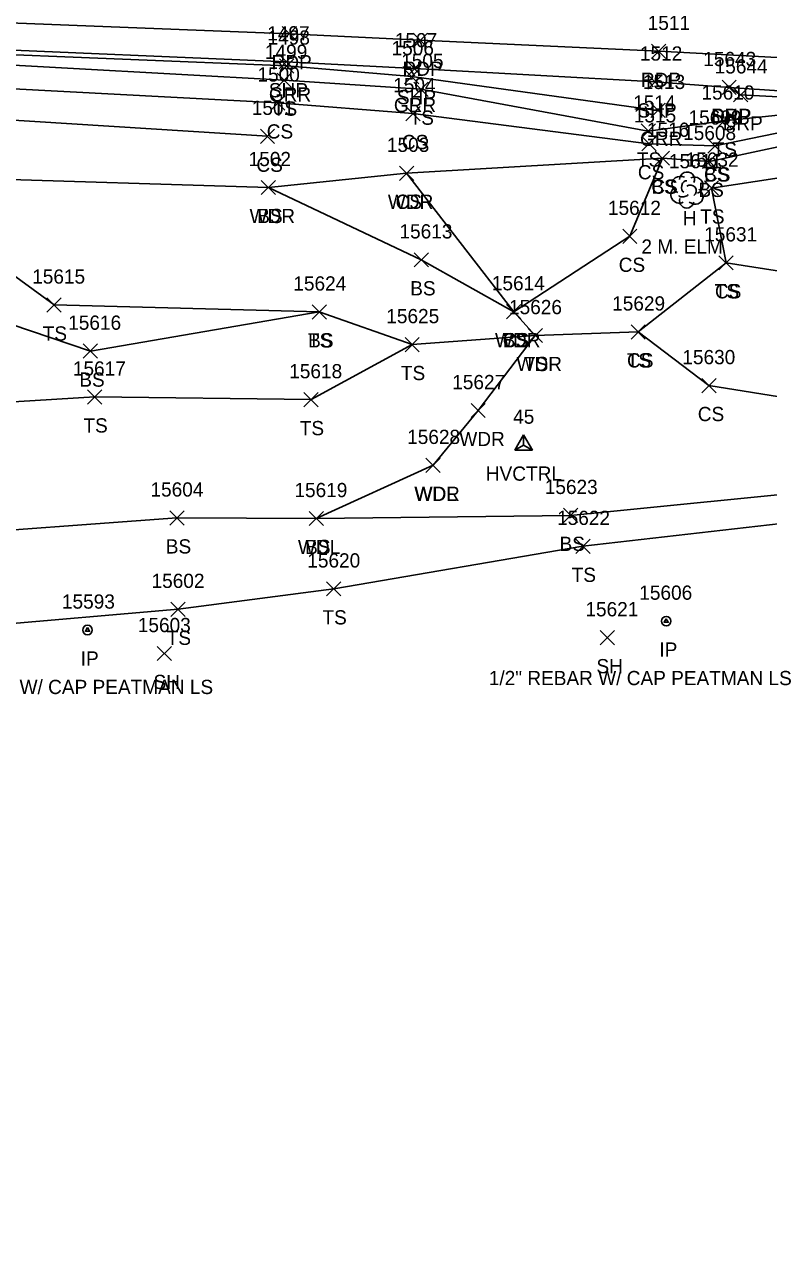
# Model space of a CAD drawing. Extents: x 1606530 to 1613020, y 784959 to 789666.
# Drawn here: x 1609388.2 to 1609492.8, y 788263.1 to 788433.6 of the extents above; entities that cross this region are included whole.
import ezdxf

# ---------------------------------------------------------------- set-up
doc = ezdxf.new("R2010")
doc.units = 0
for name, color, linetype in [('C_A', 7, 'Continuous'), ('C_I', 7, 'Continuous'), ('CPSM', 7, 'Continuous'), ('L_A', 7, 'Continuous'), ('L_C', 7, 'Continuous'), ('L_I', 7, 'Continuous'), ('L_TIC', 7, 'Continuous'), ('LAWA', 7, 'Continuous'), ('LELB', 7, 'Continuous'), ('LTD', 7, 'Continuous'), ('M_A', 7, 'Continuous'), ('M_C', 7, 'Continuous'), ('M_I', 7, 'Continuous'), ('MPIR', 7, 'Continuous'), ('P_A', 7, 'Continuous'), ('P_I', 7, 'Continuous'), ('P_TIC', 7, 'Continuous'), ('PET', 7, 'Continuous'), ('PSP', 7, 'Continuous'), ('R_A', 7, 'Continuous'), ('R_I', 7, 'Continuous'), ('R_TIC', 7, 'Continuous'), ('RDP', 7, 'Continuous'), ('RGR', 7, 'Continuous')]:
    doc.layers.add(name, color=color, linetype=linetype)

msp = doc.modelspace()

# ---------------------------------------------------------------- linework, layer by layer
at = {"layer": 'CPSM'}
for p, q in [((1609457.08, 788373.72), (1609458.33, 788375.89)), ((1609459.58, 788373.72), (1609458.33, 788375.89)), ((1609458.33, 788374.44), (1609458.33, 788375.89)), ((1609457.08, 788373.72), (1609458.33, 788374.44)), ((1609457.08, 788373.72), (1609459.58, 788373.72)), ((1609458.33, 788374.44), (1609458.33, 788374.44)), ((1609458.33, 788374.44), (1609459.58, 788373.72))]:
    msp.add_line(p, q, dxfattribs=at)
at = {"layer": 'L_TIC'}
for points in [[(1609423.69, 788424.72), (1609425.69, 788426.72)], [(1609425.69, 788424.72), (1609423.69, 788426.72)], [(1609442.9, 788423.45), (1609444.9, 788425.45)], [(1609444.9, 788423.45), (1609442.9, 788425.45)], [(1609422.8, 788421.52), (1609424.8, 788423.52)], [(1609424.8, 788421.52), (1609422.8, 788423.52)], [(1609441.79, 788420.03), (1609443.79, 788422.03)], [(1609443.79, 788420.03), (1609441.79, 788422.03)], [(1609474.84, 788417.57), (1609476.84, 788419.57)], [(1609476.84, 788417.57), (1609474.84, 788419.57)], [(1609485.48, 788418.99), (1609487.48, 788420.99)], [(1609487.48, 788418.99), (1609485.48, 788420.99)], [(1609421.35, 788416.84), (1609423.35, 788418.84)], [(1609423.35, 788416.84), (1609421.35, 788418.84)], [(1609474.94, 788415.79), (1609476.94, 788417.79)], [(1609476.94, 788415.79), (1609474.94, 788417.79)], [(1609484.22, 788415.48), (1609486.22, 788417.48)], [(1609486.22, 788415.48), (1609484.22, 788417.48)], [(1609484.22, 788415.48), (1609486.22, 788417.48)], [(1609486.22, 788415.48), (1609484.22, 788417.48)], [(1609476.83, 788413.76), (1609478.83, 788415.76)], [(1609478.83, 788413.76), (1609476.83, 788415.76)], [(1609476.83, 788413.76), (1609478.83, 788415.76)], [(1609478.83, 788413.76), (1609476.83, 788415.76)], [(1609483.45, 788413.31), (1609485.45, 788415.31)], [(1609485.45, 788413.31), (1609483.45, 788415.31)], [(1609483.45, 788413.31), (1609485.45, 788415.31)], [(1609485.45, 788413.31), (1609483.45, 788415.31)], [(1609440.9, 788411.64), (1609442.9, 788413.64)], [(1609442.9, 788411.64), (1609440.9, 788413.64)], [(1609440.9, 788411.64), (1609442.9, 788413.64)], [(1609442.9, 788411.64), (1609440.9, 788413.64)], [(1609421.47, 788409.64), (1609423.47, 788411.64)], [(1609423.47, 788409.64), (1609421.47, 788411.64)], [(1609421.47, 788409.64), (1609423.47, 788411.64)], [(1609423.47, 788409.64), (1609421.47, 788411.64)], [(1609483.73, 788409.56), (1609485.73, 788411.56)], [(1609485.73, 788409.56), (1609483.73, 788411.56)], [(1609472.25, 788402.78), (1609474.25, 788404.78)], [(1609474.25, 788402.78), (1609472.25, 788404.78)], [(1609442.96, 788399.48), (1609444.96, 788401.48)], [(1609444.96, 788399.48), (1609442.96, 788401.48)], [(1609485.77, 788399.06), (1609487.77, 788401.06)], [(1609487.77, 788399.06), (1609485.77, 788401.06)], [(1609485.77, 788399.06), (1609487.77, 788401.06)], [(1609487.77, 788399.06), (1609485.77, 788401.06)], [(1609391.36, 788393.13), (1609393.36, 788395.13)], [(1609393.36, 788393.13), (1609391.36, 788395.13)], [(1609428.62, 788392.16), (1609430.62, 788394.16)], [(1609430.62, 788392.16), (1609428.62, 788394.16)], [(1609428.62, 788392.16), (1609430.62, 788394.16)], [(1609430.62, 788392.16), (1609428.62, 788394.16)], [(1609455.94, 788392.19), (1609457.94, 788394.19)], [(1609457.94, 788392.19), (1609455.94, 788394.19)], [(1609455.94, 788392.19), (1609457.94, 788394.19)], [(1609457.94, 788392.19), (1609455.94, 788394.19)], [(1609455.94, 788392.19), (1609457.94, 788394.19)], [(1609457.94, 788392.19), (1609455.94, 788394.19)], [(1609458.97, 788388.84), (1609460.97, 788390.84)], [(1609460.97, 788388.84), (1609458.97, 788390.84)], [(1609458.97, 788388.84), (1609460.97, 788390.84)], [(1609460.97, 788388.84), (1609458.97, 788390.84)], [(1609473.42, 788389.35), (1609475.42, 788391.35)], [(1609475.42, 788389.35), (1609473.42, 788391.35)], [(1609473.42, 788389.35), (1609475.42, 788391.35)], [(1609475.42, 788389.35), (1609473.42, 788391.35)], [(1609441.68, 788387.57), (1609443.68, 788389.57)], [(1609443.68, 788387.57), (1609441.68, 788389.57)], [(1609441.68, 788387.57), (1609443.68, 788389.57)], [(1609443.68, 788387.57), (1609441.68, 788389.57)], [(1609396.47, 788386.65), (1609398.47, 788388.65)], [(1609398.47, 788386.65), (1609396.47, 788388.65)], [(1609483.36, 788381.81), (1609485.36, 788383.81)], [(1609485.36, 788381.81), (1609483.36, 788383.81)], [(1609397.08, 788380.21), (1609399.08, 788382.21)], [(1609399.08, 788380.21), (1609397.08, 788382.21)], [(1609427.47, 788379.83), (1609429.47, 788381.83)], [(1609429.47, 788379.83), (1609427.47, 788381.83)], [(1609450.94, 788378.3), (1609452.94, 788380.3)], [(1609452.94, 788378.3), (1609450.94, 788380.3)], [(1609444.61, 788370.6), (1609446.61, 788372.6)], [(1609446.61, 788370.6), (1609444.61, 788372.6)], [(1609444.61, 788370.6), (1609446.61, 788372.6)], [(1609446.61, 788370.6), (1609444.61, 788372.6)], [(1609408.62, 788363.21), (1609410.62, 788365.21)], [(1609410.62, 788363.21), (1609408.62, 788365.21)], [(1609428.2, 788363.13), (1609430.2, 788365.13)], [(1609430.2, 788363.13), (1609428.2, 788365.13)], [(1609428.2, 788363.13), (1609430.2, 788365.13)], [(1609430.2, 788363.13), (1609428.2, 788365.13)], [(1609463.94, 788363.57), (1609465.94, 788365.57)], [(1609465.94, 788363.57), (1609463.94, 788365.57)], [(1609465.67, 788359.22), (1609467.67, 788361.22)], [(1609467.67, 788359.22), (1609465.67, 788361.22)], [(1609430.66, 788353.24), (1609432.66, 788355.24)], [(1609432.66, 788353.24), (1609430.66, 788355.24)], [(1609408.78, 788350.37), (1609410.78, 788352.37)], [(1609410.78, 788350.37), (1609408.78, 788352.37)], [(1609469.08, 788346.38), (1609471.08, 788348.38)], [(1609471.08, 788346.38), (1609469.08, 788348.38)], [(1609406.85, 788344.16), (1609408.85, 788346.16)], [(1609408.85, 788344.16), (1609406.85, 788346.16)]]:
    msp.add_lwpolyline(points, dxfattribs=at)
at = {"layer": 'LAWA'}
for points in [[(1609030.56, 788292.64), (1609056.03, 788324.44), (1609082.56, 788354.61), (1609090.16, 788369.42), (1609097.26, 788381.32), (1609109.23, 788386.03), (1609115.48, 788389.16), (1609124.65, 788392.27), (1609168.82, 788397.24), (1609199.02, 788403.22), (1609247.62, 788406.18), (1609289.08, 788410.02), (1609331.31, 788409.89), (1609380.07, 788411.97), (1609422.47, 788410.64), (1609441.9, 788412.64), (1609456.94, 788393.19), (1609459.97, 788389.84), (1609451.94, 788379.3), (1609445.61, 788371.6)], [(1609429.2, 788364.13), (1609445.61, 788371.6)]]:
    msp.add_lwpolyline(points, dxfattribs=at)
at = {"layer": 'LELB'}
for points in [[(1608830.7, 788263.06), (1608870.16, 788285.39), (1608903.61, 788303.66), (1608913.17, 788310.86), (1608944.69, 788327.51), (1608982.09, 788348.33), (1609025.65, 788367.84), (1609062.43, 788383.44), (1609080.36, 788388.45), (1609093.56, 788391.85), (1609111.49, 788398.34), (1609124.29, 788403.55), (1609165.33, 788413.89), (1609196.53, 788419.38), (1609241.91, 788424.94), (1609287.83, 788428.62), (1609331.16, 788428.8), (1609379, 788428.23), (1609424.69, 788425.72), (1609443.9, 788424.45), (1609475.84, 788418.57), (1609486.48, 788419.99), (1609502.63, 788421.7)], [(1609108.11, 788392.39), (1609124.69, 788397.48), (1609165.9, 788409.88), (1609197.34, 788410.75), (1609242.01, 788420.69), (1609288.52, 788423.98), (1609330.87, 788426.64), (1609378.66, 788424.92), (1609423.8, 788422.52), (1609442.79, 788421.03), (1609475.94, 788416.79), (1609485.22, 788416.48)], [(1609199.02, 788403.22), (1609245.4, 788416.55), (1609288, 788417.43), (1609333.16, 788421.05), (1609378.48, 788420.63), (1609422.35, 788417.84)], [(1609485.22, 788416.48), (1609502.09, 788419.94), (1609505.42, 788420.27), (1609505.55, 788418.27)], [(1609229.47, 788383.53), (1609235.87, 788391.77), (1609234.95, 788395.09), (1609256.53, 788397.81), (1609290, 788390.61), (1609315.27, 788387.55), (1609343.3, 788388.82), (1609351.97, 788404.1), (1609376.56, 788405.69), (1609392.36, 788394.13), (1609429.62, 788393.16), (1609442.68, 788388.57), (1609459.97, 788389.84), (1609474.42, 788390.35), (1609486.77, 788400.06), (1609484.73, 788410.56), (1609507.1, 788413.97), (1609507.85, 788418.71)], [(1609484.45, 788414.31), (1609501.55, 788417.96), (1609505.55, 788418.27)], [(1609441.9, 788412.64), (1609477.83, 788414.76), (1609473.25, 788403.78), (1609456.94, 788393.19)], [(1609477.83, 788414.76), (1609484.45, 788414.31)], [(1609422.47, 788410.64), (1609443.96, 788400.48), (1609456.94, 788393.19)], [(1609486.77, 788400.06), (1609518.48, 788395.11)], [(1609343.3, 788388.82), (1609372.31, 788396.17), (1609397.47, 788387.65), (1609429.62, 788393.16)], [(1609235.87, 788391.77), (1609256.08, 788384.31), (1609291.75, 788375.34), (1609316.49, 788370.01), (1609344.99, 788380.11), (1609370.61, 788379.55), (1609398.08, 788381.21), (1609428.47, 788380.83), (1609442.68, 788388.57)], [(1609474.42, 788390.35), (1609484.36, 788382.81), (1609503.91, 788379.7), (1609526.85, 788382.89)], [(1609374.03, 788361.62), (1609409.62, 788364.21), (1609429.2, 788364.13), (1609464.94, 788364.57), (1609503.84, 788368.43), (1609529.95, 788369.13)], [(1609382.71, 788349.03), (1609409.78, 788351.37), (1609431.66, 788354.24), (1609466.67, 788360.22), (1609502.72, 788364.36), (1609529.95, 788369.13)]]:
    msp.add_lwpolyline(points, dxfattribs=at)
at = {"layer": 'LTD'}
msp.add_line((1609481.26, 788410.34), (1609481.26, 788410.34), dxfattribs=at)
msp.add_line((1609481.26, 788410.34), (1609481.26, 788410.34), dxfattribs=at)
msp.add_arc((1609481.3, 788411.77), 1.05, 335.5272, 180.9563, dxfattribs=at)
for centre, major_axis, ratio, start_param, end_param in [((1609480.46, 788411.01), (1.21, -0.51), 0.895232, 1.570796, 4.712389), ((1609481.05, 788410.8), (-0.208, -0.792), 0.645439, 3.141593, 6.283185), ((1609481.76, 788410.17), (-0.5, 0.667), 0.989748, 3.141593, 6.283185), ((1609482.3, 788410.92), (-1.14, -0.48), 0.949671, 1.570796, 4.712389), ((1609480.17, 788409.63), (0.58, -1.04), 0.959034, 3.141593, 6.283185), ((1609480.8, 788409.59), (-0.625, -0.083), 0.423636, 0, 3.141593), ((1609482.26, 788409.51), (-1.09, 0.79), 0.841452, 1.570796, 4.712389), ((1609481.26, 788408.84), (0.26, 1.06), 0.942809, 1.570796, 4.712389)]:
    msp.add_ellipse(centre, major_axis=major_axis, ratio=ratio, start_param=start_param, end_param=end_param, dxfattribs=at)
at = {"layer": 'MPIR'}
for points in [[(1609478.36, 788350.05), (1609478.07, 788349.55), (1609478.64, 788349.55)], [(1609397.06, 788348.79), (1609396.77, 788348.29), (1609397.35, 788348.29)]]:
    msp.add_lwpolyline(points, close=True, dxfattribs=at)
for centre in [(1609478.36, 788349.71), (1609397.06, 788348.46)]:
    msp.add_circle(centre, 0.667, dxfattribs=at)
at = {"layer": 'P_TIC'}
for points in [[(1609424.43, 788431.25), (1609426.43, 788433.25)], [(1609426.43, 788431.25), (1609424.43, 788433.25)], [(1609442.83, 788430.33), (1609444.83, 788432.33)], [(1609444.83, 788430.33), (1609442.83, 788432.33)], [(1609476.32, 788428.78), (1609478.32, 788430.78)], [(1609478.32, 788428.78), (1609476.32, 788430.78)], [(1609424.01, 788427.31), (1609426.01, 788429.31)], [(1609426.01, 788427.31), (1609424.01, 788429.31)], [(1609442, 788426.34), (1609444, 788428.34)], [(1609444, 788426.34), (1609442, 788428.34)], [(1609475.79, 788424.47), (1609477.79, 788426.47)], [(1609477.79, 788424.47), (1609475.79, 788426.47)], [(1609486.21, 788423.7), (1609488.21, 788425.7)], [(1609488.21, 788423.7), (1609486.21, 788425.7)]]:
    msp.add_lwpolyline(points, dxfattribs=at)
at = {"layer": 'PET'}
msp.add_lwpolyline([(1608827.2, 788266.24), (1608867.86, 788290.54), (1608906.68, 788312.86), (1608942.68, 788332.75), (1608980.54, 788352.16), (1609023.57, 788373.22), (1609061.44, 788389.9), (1609090.8, 788401.17), (1609121.92, 788410.09), (1609165.17, 788420), (1609195.85, 788425.54), (1609240.14, 788431.13), (1609287.88, 788434.37), (1609331.48, 788435.11), (1609378.89, 788434.05), (1609425.43, 788432.25), (1609443.83, 788431.33), (1609477.32, 788429.78), (1609518.44, 788427.6), (1609569.18, 788424.68), (1609602.99, 788422.58), (1609641.45, 788420.37), (1609681.7, 788417.92), (1609727.38, 788415.53)], dxfattribs=at)
at = {"layer": 'PSP'}
msp.add_lwpolyline([(1609378.92, 788430.28), (1609425.01, 788428.31), (1609443, 788427.34), (1609476.79, 788425.47), (1609487.21, 788424.7), (1609502.75, 788423.67), (1609527.75, 788422.97), (1609569.13, 788420.68), (1609592.88, 788419.12), (1609602.1, 788418.65), (1609640.72, 788416.23), (1609676.37, 788413.47), (1609681.63, 788413.32), (1609727.4, 788411.58)], dxfattribs=at)
at = {"layer": 'R_TIC'}
for points in [[(1609424.05, 788426.72), (1609426.05, 788428.72)], [(1609426.05, 788426.72), (1609424.05, 788428.72)], [(1609441.61, 788425.23), (1609443.61, 788427.23)], [(1609443.61, 788425.23), (1609441.61, 788427.23)], [(1609486.21, 788423.7), (1609488.21, 788425.7)], [(1609488.21, 788423.7), (1609486.21, 788425.7)], [(1609487.81, 788422.66), (1609489.81, 788424.66)], [(1609489.81, 788422.66), (1609487.81, 788424.66)], [(1609476.2, 788420.48), (1609478.2, 788422.48)], [(1609478.2, 788420.48), (1609476.2, 788422.48)]]:
    msp.add_lwpolyline(points, dxfattribs=at)
at = {"layer": 'RDP'}
msp.add_lwpolyline([(1609487.21, 788424.7), (1609488.81, 788423.66), (1609498.54, 788423.13), (1609502.75, 788423.67)], dxfattribs=at)
at = {"layer": 'RGR'}
msp.add_lwpolyline([(1609093.56, 788395.55), (1609123.33, 788406.23), (1609196.19, 788421.65), (1609241.24, 788427.81), (1609287.73, 788430.93), (1609331.28, 788431.08), (1609378.86, 788429.59), (1609425.05, 788427.72), (1609442.61, 788426.23), (1609477.2, 788421.48)], dxfattribs=at)

# ---------------------------------------------------------------- texts
at = {"layer": 'C_A'}
msp.add_text('HVCTRL', height=2, dxfattribs=at).set_placement((1609453.02, 788369.44))
at = {"layer": 'C_I'}
msp.add_text('45', height=2, dxfattribs=at).set_placement((1609456.86, 788377.44))
at = {"layer": 'L_A'}
for s, p in [('TS', (1609423.1, 788420.72)), ('TS', (1609442.31, 788419.45)), ('CS', (1609422.24, 788417.52)), ('CS', (1609441.23, 788416.03)), ('TS', (1609484.89, 788414.99)), ('CS', (1609420.79, 788412.84)), ('TS', (1609474.25, 788413.57)), ('CS', (1609474.38, 788411.79)), ('CS', (1609483.67, 788411.48)), ('BS', (1609483.67, 788411.48)), ('CS', (1609476.27, 788409.76)), ('BS', (1609476.27, 788409.76)), ('BS', (1609482.89, 788409.31)), ('BS', (1609482.89, 788409.31)), ('WDR', (1609439.26, 788407.64)), ('CS', (1609440.34, 788407.64)), ('WDR', (1609419.83, 788405.64)), ('BS', (1609420.91, 788405.64)), ('TS', (1609483.14, 788405.56)), ('H', (1609480.69, 788405.34)), ('CS', (1609471.69, 788398.78)), ('BS', (1609442.4, 788395.48)), ('TS', (1609485.18, 788395.06)), ('CS', (1609485.21, 788395.06)), ('TS', (1609390.77, 788389.13)), ('TS', (1609428.03, 788388.16)), ('BS', (1609428.06, 788388.16)), ('WDR', (1609454.31, 788388.19)), ('CS', (1609455.39, 788388.19)), ('BS', (1609455.39, 788388.19)), ('TS', (1609472.83, 788385.35)), ('CS', (1609472.86, 788385.35)), ('TS', (1609441.09, 788383.57)), ('TS', (1609441.09, 788383.57)), ('WDR', (1609457.33, 788384.84)), ('TS', (1609458.38, 788384.84)), ('BS', (1609395.91, 788382.65)), ('CS', (1609482.8, 788377.81)), ('TS', (1609396.49, 788376.21)), ('TS', (1609426.88, 788375.83)), ('WDR', (1609449.3, 788374.3)), ('WDR', (1609442.97, 788366.6)), ('WDL', (1609443.03, 788366.6)), ('BS', (1609463.38, 788359.57)), ('BS', (1609408.06, 788359.21)), ('WDL', (1609426.62, 788359.13)), ('BS', (1609427.64, 788359.13)), ('TS', (1609465.08, 788355.22)), ('TS', (1609430.07, 788349.24)), ('TS', (1609408.19, 788346.37)), ('SH', (1609468.56, 788342.38)), ('SH', (1609406.34, 788340.16))]:
    msp.add_text(s, height=2, dxfattribs=at).set_placement(p)
at = {"layer": 'L_C'}
msp.add_text('2 M. ELM', height=2, dxfattribs=at).set_placement((1609474.88, 788401.34))
at = {"layer": 'L_I'}
for s, p in [('1499', (1609421.99, 788428.72)), ('1505', (1609441.13, 788427.45)), ('1500', (1609420.94, 788425.52)), ('1504', (1609440.01, 788424.03)), ('15610', (1609483.32, 788422.99)), ('1501', (1609420.14, 788420.84)), ('1514', (1609473.72, 788421.57)), ('1515', (1609473.81, 788419.79)), ('15609', (1609481.5, 788419.48)), ('15609', (1609481.5, 788419.48)), ('1516', (1609475.65, 788417.76)), ('1516', (1609475.65, 788417.76)), ('15608', (1609480.74, 788417.31)), ('15608', (1609480.74, 788417.31)), ('1503', (1609439.13, 788415.64)), ('1503', (1609439.13, 788415.64)), ('1502', (1609419.7, 788413.64)), ('1502', (1609419.7, 788413.64)), ('15611', (1609478.75, 788413.34)), ('15632', (1609481.09, 788413.56)), ('15612', (1609470.18, 788406.78)), ('15613', (1609440.89, 788403.48)), ('15631', (1609483.7, 788403.06)), ('15631', (1609483.7, 788403.06)), ('15615', (1609389.29, 788397.13)), ('15624', (1609425.98, 788396.16)), ('15624', (1609425.98, 788396.16)), ('15614', (1609453.87, 788396.19)), ('15614', (1609453.87, 788396.19)), ('15614', (1609453.87, 788396.19)), ('15626', (1609456.28, 788392.84)), ('15626', (1609456.28, 788392.84)), ('15629', (1609470.77, 788393.35)), ('15629', (1609470.77, 788393.35)), ('15616', (1609394.35, 788390.65)), ('15625', (1609439.04, 788391.57)), ('15625', (1609439.04, 788391.57)), ('15630', (1609480.63, 788385.81)), ('15617', (1609395.01, 788384.21)), ('15618', (1609425.4, 788383.83)), ('15627', (1609448.3, 788382.3)), ('15628', (1609441.97, 788374.6)), ('15628', (1609441.97, 788374.6)), ('15604', (1609405.91, 788367.21)), ('15619', (1609426.13, 788367.13)), ('15619', (1609426.13, 788367.13)), ('15623', (1609461.3, 788367.57)), ('15622', (1609463.03, 788363.22)), ('15620', (1609427.94, 788357.24)), ('15602', (1609406.06, 788354.37)), ('15621', (1609467.01, 788350.38)), ('15603', (1609404.13, 788348.16))]:
    msp.add_text(s, height=2, dxfattribs=at).set_placement(p)
at = {"layer": 'M_A'}
for p in [(1609477.4, 788344.71), (1609396.11, 788343.46)]:
    msp.add_text('IP', height=2, dxfattribs=at).set_placement(p)
at = {"layer": 'M_C'}
for p in [(1609453.44, 788340.71), (1609372.15, 788339.46)]:
    msp.add_text('1/2" REBAR W/ CAP PEATMAN LS', height=2, dxfattribs=at).set_placement(p)
at = {"layer": 'M_I'}
for s, p in [('15606', (1609474.58, 788352.71)), ('15593', (1609393.47, 788351.46))]:
    msp.add_text(s, height=2, dxfattribs=at).set_placement(p)
at = {"layer": 'P_A'}
for s, p in [('RDP', (1609422.92, 788427.25)), ('RDP', (1609441.32, 788426.33)), ('RDP', (1609474.81, 788424.78)), ('SHP', (1609422.54, 788423.31)), ('SHP', (1609440.53, 788422.34)), ('SHP', (1609474.33, 788420.47)), ('SHP', (1609484.74, 788419.7))]:
    msp.add_text(s, height=2, dxfattribs=at).set_placement(p)
at = {"layer": 'P_I'}
for s, p in [('1497', (1609422.31, 788431.31)), ('1511', (1609475.76, 788432.78)), ('1507', (1609440.23, 788430.34)), ('1512', (1609474.67, 788428.47)), ('15643', (1609483.57, 788427.7))]:
    msp.add_text(s, height=2, dxfattribs=at).set_placement(p)
at = {"layer": 'R_A'}
for s, p in [('GRR', (1609422.54, 788422.72)), ('GRR', (1609440.1, 788421.23)), ('DRP', (1609484.69, 788419.7)), ('DRP', (1609486.29, 788418.66)), ('GRR', (1609474.69, 788416.48))]:
    msp.add_text(s, height=2, dxfattribs=at).set_placement(p)
at = {"layer": 'R_I'}
for s, p in [('1498', (1609422.36, 788430.72)), ('1506', (1609439.78, 788429.23)), ('15643', (1609483.57, 788427.7)), ('15644', (1609485.17, 788426.66)), ('1513', (1609475.08, 788424.48))]:
    msp.add_text(s, height=2, dxfattribs=at).set_placement(p)

doc.saveas('drawing.dxf')
